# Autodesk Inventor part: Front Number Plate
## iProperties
Shininess: 21.0
Angle Display Precision: 2
Document Length Units: 11269
Document Angle Units: 11279
Document Time Units: 11290
Document Mass Units: 11283
Document Length Units Precision: 3
Document Angle Units Precision: 2
Compacted: True
Created: 2001-08
Part Number: Front Number Plate
Document SubType Name: Modeling
Designer: Martin Budgell
Density: 0.0
Volumn: 0.0
Area: 0.0
PropertySet Name: Model Information
Control State: 0
Master: False
Checked Out: False
Author: Martin Budgell
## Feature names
1. Extrusion1
2. Fillet1
3. Extrusion2
4. Fillet2
5. Extrusion3
